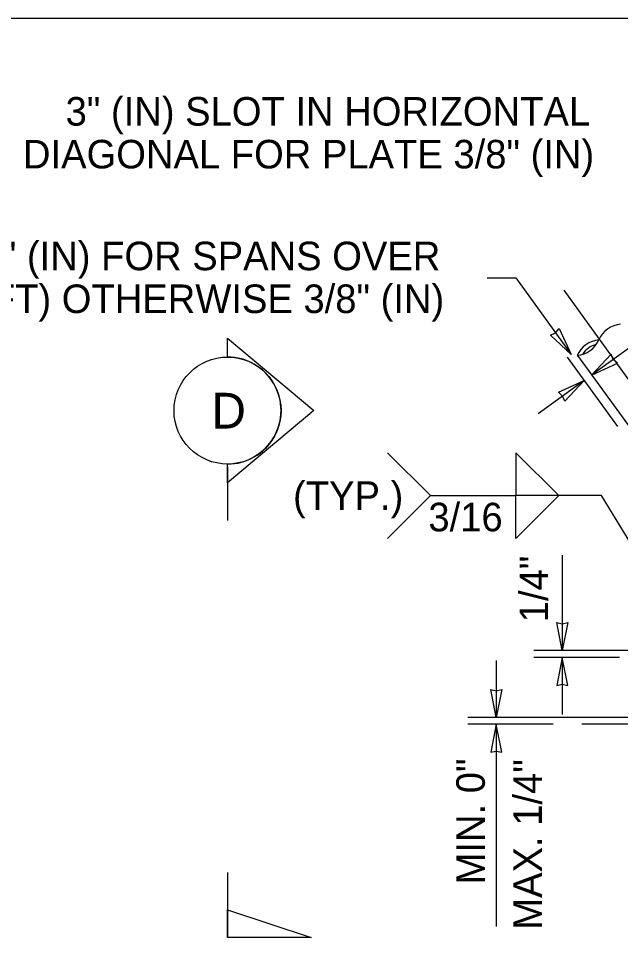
# Model space of a CAD drawing. Extents: x 99862 to 104211, y 98939 to 111076.
# Drawn here: x 101713 to 102050, y 107560 to 108075 of the extents above; entities that cross this region are included whole.
import ezdxf

# ---------------------------------------------------------------- set-up
doc = ezdxf.new("R2010")
doc.units = 0
for name, color, linetype in [('Level 15', 7, 'Continuous'), ('Level 20', 7, 'Continuous'), ('Level 5', 7, 'Continuous'), ('Level 60', 7, 'Continuous'), ('Level 9', 7, 'Continuous')]:
    doc.layers.add(name, color=color, linetype=linetype)

msp = doc.modelspace()

# ---------------------------------------------------------------- linework, layer by layer
at = {"layer": 'Level 15'}
for p, q in [((101975.58, 107929.6), (101991.58, 107929.6)), ((101991.58, 107929.6), (102022.65, 107886.54)), ((102191.51, 107683.1), (102018.62, 107922.68)), ((102060, 107893.77), (102034.05, 107875.04)), ((102048.71, 107846.16), (102020.62, 107885.08)), ((102029.98, 107872.1), (102004.03, 107853.38)), ((101919.65, 107831.49), (101943.65, 107807.49)), ((101991.65, 107831.49), (101991.65, 107807.49)), ((101991.65, 107831.49), (102015.65, 107807.49)), ((101919.65, 107783.49), (101943.65, 107807.49)), ((101943.65, 107807.49), (101991.65, 107807.49)), ((102039.65, 107807.49), (101991.65, 107807.49)), ((101991.65, 107783.49), (101991.65, 107807.49)), ((101991.65, 107783.49), (102015.65, 107807.49)), ((102094.87, 107716.8), (102039.65, 107807.49)), ((102017.65, 107774.05), (102017.65, 107720.67)), ((102123.27, 107720.67), (102001.65, 107720.67)), ((101980.59, 107715.1), (101980.59, 107683.1)), ((102049.65, 107716.8), (102001.65, 107716.8)), ((102017.65, 107716.8), (102017.65, 107684.8)), ((102175.51, 107683.1), (101964.59, 107683.1)), ((102012.59, 107679.35), (101964.59, 107679.35)), ((101980.59, 107679.35), (101980.59, 107565.91)), ((102354.43, 107679.35), (102028.59, 107679.35))]:
    msp.add_line(p, q, dxfattribs=at)
for points in [[(102022.65, 107886.54), (102010.95, 107897.49), (102013.87, 107898.71), (102015.95, 107901.1)], [(102034.05, 107875.04), (102048.61, 107881.74), (102046.21, 107883.82), (102045, 107886.74)], [(102029.98, 107872.1), (102019.04, 107860.4), (102017.82, 107863.33), (102015.43, 107865.4)], [(102017.65, 107720.67), (102014.56, 107736.39), (102017.65, 107735.67), (102020.73, 107736.39)], [(102017.65, 107716.8), (102014.56, 107701.08), (102017.65, 107701.81), (102020.73, 107701.08)], [(101980.59, 107683.1), (101977.51, 107698.82), (101980.59, 107698.1), (101983.68, 107698.82)], [(101980.59, 107679.35), (101977.51, 107663.62), (101980.59, 107664.35), (101983.68, 107663.62)]]:
    msp.add_lwpolyline(points, close=True, dxfattribs=at)
at = {"layer": 'Level 5'}
msp.add_line((102026.12, 107886.03), (102088.77, 107799.84), dxfattribs=at)
for centre, radius, start, end in [((102051.86, 107888.74), 15, 96.0122, 156.0122), ((102024.45, 107900.94), 15, 276.0122, 336.0122), ((102039.73, 107879.92), 15, 96.0122, 156.0122), ((102039.73, 107879.92), 12.69, 103.9332, 148.0912)]:
    msp.add_arc(centre, radius, start, end, dxfattribs=at)
at = {"layer": 'Level 60'}
msp.add_line((103150, 108075), (100000, 108075), dxfattribs=at)
at = {"layer": 'Level 9'}
for p, q in [((101829.93, 107885.18), (101829.93, 107895.78)), ((101829.93, 107895.78), (101878.39, 107855.18)), ((101878.39, 107855.18), (101829.93, 107814.58)), ((101829.93, 107814.58), (101829.93, 107825.18)), ((101829.93, 107823.62), (101829.93, 107793.62)), ((101829.93, 107596.28), (101829.93, 107559.75))]:
    msp.add_line(p, q, dxfattribs=at)
msp.add_lwpolyline([(101829.93, 107575.28), (101876.81, 107559.75), (101829.93, 107559.75)], close=True, dxfattribs=at)
msp.add_circle((101829.93, 107855.18), 30, dxfattribs=at)
msp.add_arc((101829.93, 107855.18), 30, 269.9978, 90.0022, dxfattribs=at)

# ---------------------------------------------------------------- texts
at = {"layer": 'Level 15'}
for s, p in [('3" (IN) SLOT IN HORIZONTAL', (101739.15, 108014.9)), ('DIAGONAL FOR PLATE 3/8" (IN)', (101715.24, 107990.9)), ('3/4" (IN) FOR SPANS OVER', (101674.18, 107933.84)), ('120\' (FT) OTHERWISE 3/8" (IN)', (101644.93, 107909.84)), ('3/16', (101942.56, 107787.49))]:
    msp.add_text(s, height=16, dxfattribs=at).set_placement(p)
at = {"layer": 'Level 20'}
for s, height, p in [('D', 20, (101820.94, 107845.12)), ('(TYP.)', 16, (101866.68, 107799.49))]:
    msp.add_text(s, height=height, dxfattribs=at).set_placement(p)
for s, p in [('1/4"', (102009.65, 107736.5)), ('MIN. 0"', (101974.21, 107589.56)), ('MAX. 1/4"', (102006.21, 107564.18))]:
    msp.add_text(s, height=16, rotation=90, dxfattribs=at).set_placement(p)

doc.saveas('drawing.dxf')
